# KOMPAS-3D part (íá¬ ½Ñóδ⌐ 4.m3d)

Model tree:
1. Эскиз:1
2. Операция выдавливания:1
     Расстояние 1 = 10.5
3. Эскиз:2
4. Операция выдавливания:2
     Расстояние 1 = 2.5
5. Эскиз:3
6. Вырезать элемент выдавливания:1
     Расстояние 1 = 34.8
7. Скругление:2
     Радиус = 1
8. Скругление:3
     Радиус = 2
9. Скругление:4
     Радиус = 2
10. Скругление:5
     Радиус = 0.5
11. Эскиз:4
12. Операция выдавливания:3
     Расстояние 1 = 0.1
13. Эскиз:5
14. Операция выдавливания:4
     Расстояние 1 = 0.5
15. Скругление:6
     Радиус = 0.5
16. Эскиз:6
17. Операция выдавливания:5
     Расстояние 1 = 0.5
18. Скругление:7
     Радиус = 0.5
19. Эскиз:7
20. Операция выдавливания:6
     Расстояние 1 = 0.32
21. Эскиз:8
22. Операция выдавливания:7
     Расстояние 1 = 0.32; Расстояние 2 = 3
23. Эскиз:9
24. Вырезать элемент выдавливания:2
     Расстояние 1 = 1; Угол 1 = 10
25. Скругление:8
     Радиус = 0.5
26. Эскиз:10
27. Вырезать элемент выдавливания:3
     Расстояние 1 = 0.5; Угол 1 = 10
28. Эскиз:11
29. Вырезать элемент выдавливания:4
     Расстояние 1 = 0.5; Угол 1 = 10
30. Эскиз:12
31. Операция выдавливания:8
     Расстояние 1 = 0.5; Расстояние 2 = 3
32. Скругление:9
     Радиус = 0.5
33. Эскиз:13
34. Операция выдавливания:9
     Расстояние 1 = 0.5; Расстояние 2 = 3
35. Эскиз:14
36. Операция выдавливания:10
     Расстояние 1 = 0.3; Расстояние 2 = 3
37. Скругление:10
     Радиус = 0.5
38. Скругление:11
     Радиус = 0.3
39. Эскиз:15
40. Вырезать элемент выдавливания:5
     Расстояние 1 = 0.3; Угол 1 = 10
41. Скругление:12
     Радиус = 0.3
42. Эскиз:17
43. Вырезать элемент выдавливания:6
     Расстояние 1 = 4.9
44. Скругление:14
     Радиус = 1
45. Скругление:15
     Радиус = 1

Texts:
  бак левый 4
  Сплав АЛ8  ГОСТ 1583-93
